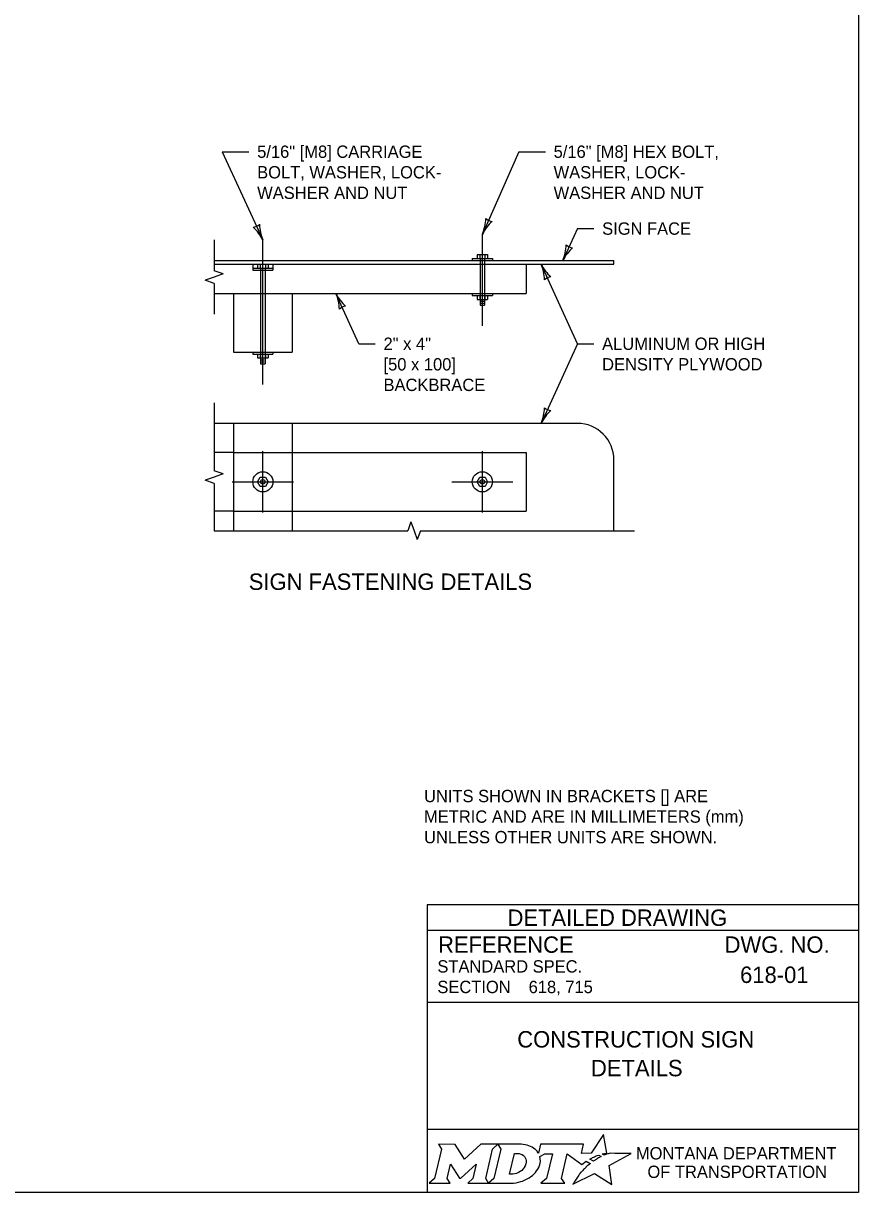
# Model space of a CAD drawing. Extents: x 49991.4 to 50021, y 49987.6 to 50011.4.
# Drawn here: x 50012.69 to 50016.75, y 49987.8 to 49993.49 of the extents above; entities that cross this region are included whole.
import ezdxf

# ---------------------------------------------------------------- set-up
doc = ezdxf.new("R2010")
doc.units = 0
for name, color, linetype in [('Default', 7, 'Continuous'), ('Level 1', 7, 'Continuous'), ('Level 2', 7, 'Continuous'), ('Level 3', 7, 'Continuous'), ('Level 4', 7, 'Continuous'), ('Level 5', 7, 'Continuous'), ('Level 6', 7, 'Continuous')]:
    doc.layers.add(name, color=color, linetype=linetype)

msp = doc.modelspace()

# ---------------------------------------------------------------- linework, layer by layer
at = {"layer": 'Default'}
for points in [[(50015.5126, 49987.9811), (50015.5023, 49987.9867), (50015.5139, 49987.9895), (50015.5255, 49987.9915), (50015.5081, 49988.0816), (50015.4486, 49987.9903), (50015.4013, 49987.9896), (50015.4116, 49988.0337), (50015.2024, 49988.0338), (50015.1923, 49987.9913), (50015.1865, 49987.9996)], [(50014.7056, 49988.0338), (50014.7197, 49988.0104), (50014.6862, 49987.8671), (50014.6605, 49987.8446), (50014.7621, 49987.8446), (50014.7486, 49987.8674), (50014.7648, 49987.9375), (50014.8085, 49987.8685), (50014.8138, 49987.8685), (50014.8889, 49987.938), (50014.8725, 49987.8669), (50014.8478, 49987.8449), (50014.9494, 49987.8449), (50014.9356, 49987.8682), (50014.9688, 49988.0106)], [(50014.9688, 49988.0106), (50014.9941, 49988.0338), (50014.9117, 49988.0338), (50014.8321, 49987.9608), (50014.7876, 49988.0335), (50014.7056, 49988.0338)], [(50015.1077, 49988.0338), (50014.9941, 49988.0338), (50015.0088, 49988.0109), (50014.9749, 49987.8671), (50014.9494, 49987.8449), (50015.06, 49987.8449)], [(50015.1317, 49987.9471), (50015.1305, 49987.939), (50015.1273, 49987.9297), (50015.1231, 49987.9215), (50015.1175, 49987.914), (50015.111, 49987.9071), (50015.1031, 49987.9008), (50015.0948, 49987.8961), (50015.0857, 49987.8922), (50015.0766, 49987.8899), (50015.0674, 49987.889), (50015.0515, 49987.889), (50015.0751, 49987.989), (50015.0911, 49987.989), (50015.0987, 49987.9884), (50015.1063, 49987.9865), (50015.1129, 49987.9835), (50015.119, 49987.9793), (50015.1238, 49987.9743), (50015.1275, 49987.9683), (50015.1302, 49987.9621), (50015.1318, 49987.9547), (50015.1318, 49987.9517), (50015.1317, 49987.9471)], [(50015.1991, 49987.9747), (50015.2237, 49987.9878), (50015.2606, 49987.9878), (50015.232, 49987.8673), (50015.2045, 49987.8446), (50015.3207, 49987.8446), (50015.3037, 49987.8675), (50015.3319, 49987.9877), (50015.4032, 49987.936), (50015.4243, 49987.9511), (50015.444, 49987.9402)], [(50015.3882, 49987.8843), (50015.3729, 49987.8599), (50015.3682, 49987.8524), (50015.3624, 49987.8438), (50015.3601, 49987.8395), (50015.4654, 49987.8926), (50015.5493, 49987.8375), (50015.5362, 49987.9302), (50015.6431, 49987.9886), (50015.5938, 49987.9894), (50015.5637, 49987.9898), (50015.5429, 49987.9901), (50015.5361, 49987.9886), (50015.5312, 49987.9874), (50015.5228, 49987.9851), (50015.5126, 49987.9811)], [(50015.4622, 49987.9535), (50015.4598, 49987.9518), (50015.4415, 49987.9614), (50015.4518, 49987.9671), (50015.4559, 49987.9693), (50015.4645, 49987.9733), (50015.4702, 49987.9759), (50015.4781, 49987.9789), (50015.4854, 49987.9816), (50015.4972, 49987.9742), (50015.4932, 49987.9721), (50015.4886, 49987.9696), (50015.4844, 49987.9674), (50015.4794, 49987.9645), (50015.4775, 49987.9634), (50015.4748, 49987.9618), (50015.4723, 49987.9604), (50015.47, 49987.9588), (50015.4674, 49987.957), (50015.4647, 49987.9552), (50015.4622, 49987.9535)], [(50015.1057, 49987.8522), (50015.1141, 49987.8548), (50015.1271, 49987.8602), (50015.1475, 49987.8712)], [(50015.4021, 49987.9004), (50015.4021, 49987.9004)]]:
    msp.add_lwpolyline(points, dxfattribs=at)
for centre, radius, start, end in [((50015.0868, 49987.9727), 0.1183, 300.9103, 339.1383), ((50015.1308, 49987.9554), 0.0709, 339.5329, 15.8582)]:
    msp.add_arc(centre, radius, start, end, dxfattribs=at)
for centre, major_axis, ratio, start_param, end_param in [((50015.1056, 49987.9864), (0.0834, -0.0037), 0.568097, 0.61298, 1.570796), ((50015.1612, 49987.9937), (0.0361, -0.0295), 0.469099, 1.225588, 1.570796), ((50015.4329, 49987.9305), (-0.0112, -0.0097), 0.021651, 3.157348, 6.283185), ((50015.3952, 49987.8923), (-0.00694, -0.00806), 0.008222, 0, 3.137361), ((50015.4119, 49987.9106), (-0.0098, -0.0102), 0.016458, 3.141593, 6.279097), ((50015.0603, 49987.9932), (0, 0.1484), 0.987302, 3.139398, 3.456847)]:
    msp.add_ellipse(centre, major_axis=major_axis, ratio=ratio, start_param=start_param, end_param=end_param, dxfattribs=at)
at = {"layer": 'Level 1'}
for p, q in [((50013.614, 49992.3335), (50015.5597, 49992.3335)), ((50013.614, 49992.3156), (50015.1326, 49992.3156)), ((50013.8258, 49992.3156), (50013.8771, 49992.3156)), ((50014.8703, 49992.343), (50014.9683, 49992.343)), ((50014.8703, 49992.343), (50014.8703, 49992.3335)), ((50014.8938, 49992.362), (50014.8938, 49992.343)), ((50014.8938, 49992.362), (50014.9451, 49992.362)), ((50014.9068, 49992.362), (50014.9068, 49992.343)), ((50014.9321, 49992.362), (50014.9321, 49992.343)), ((50014.9451, 49992.362), (50014.9451, 49992.343)), ((50014.9683, 49992.343), (50014.9683, 49992.3335)), ((50015.1326, 49992.3156), (50015.1326, 49992.1731)), ((50015.1326, 49992.3156), (50015.5597, 49992.3156)), ((50015.5597, 49992.3156), (50015.5597, 49992.3335)), ((50013.614, 49992.1731), (50015.1326, 49992.1731)), ((50013.709, 49992.1731), (50013.709, 49991.8881)), ((50013.994, 49992.1731), (50013.994, 49991.8881)), ((50014.8703, 49992.1731), (50014.8703, 49992.1636)), ((50014.8703, 49992.1636), (50014.9683, 49992.1636)), ((50014.8938, 49992.1636), (50014.8938, 49992.1446)), ((50014.8938, 49992.1446), (50014.9451, 49992.1446)), ((50014.9068, 49992.1636), (50014.9068, 49992.1446)), ((50014.9082, 49992.1446), (50014.9082, 49992.1161)), ((50014.913, 49992.1351), (50014.9257, 49992.1351)), ((50014.9305, 49992.1446), (50014.9305, 49992.1161)), ((50014.9321, 49992.1636), (50014.9321, 49992.1446)), ((50014.9451, 49992.1636), (50014.9451, 49992.1446)), ((50014.9683, 49992.1731), (50014.9683, 49992.1636)), ((50014.9082, 49992.1161), (50014.9305, 49992.1161)), ((50014.913, 49992.1256), (50014.9257, 49992.1256)), ((50013.709, 49991.8881), (50013.994, 49991.8881)), ((50013.8023, 49991.8881), (50013.8023, 49991.8786)), ((50013.8023, 49991.8786), (50013.9004, 49991.8786)), ((50013.8258, 49991.8786), (50013.8258, 49991.8596)), ((50013.8258, 49991.8596), (50013.8771, 49991.8596)), ((50013.8388, 49991.8786), (50013.8388, 49991.8596)), ((50013.8402, 49991.8596), (50013.8402, 49991.8311)), ((50013.8625, 49991.8596), (50013.8625, 49991.8311)), ((50013.8641, 49991.8786), (50013.8641, 49991.8596)), ((50013.8771, 49991.8786), (50013.8771, 49991.8596)), ((50013.9004, 49991.8881), (50013.9004, 49991.8786)), ((50013.8402, 49991.8311), (50013.8625, 49991.8311)), ((50013.845, 49991.8501), (50013.8577, 49991.8501)), ((50013.845, 49991.8406), (50013.8577, 49991.8406)), ((50015.382, 49991.5414), (50013.614, 49991.5414)), ((50013.709, 49991.5414), (50013.709, 49991.0192)), ((50013.994, 49991.5414), (50013.994, 49991.0192)), ((50013.709, 49991.3992), (50013.614, 49991.3992)), ((50013.994, 49991.3992), (50015.1326, 49991.3992)), ((50015.1326, 49991.3992), (50015.1326, 49991.1142)), ((50015.5597, 49991.0192), (50015.5597, 49991.3634)), ((50013.709, 49991.1142), (50013.614, 49991.1142)), ((50013.994, 49991.1142), (50015.1326, 49991.1142)), ((50016.3862, 49988.8587), (50016.3862, 49988.8587)), ((50015.1444, 49988.7993), (50015.1444, 49988.7993)), ((50015.7001, 49988.4747), (50015.7001, 49988.4747))]:
    msp.add_line(p, q, dxfattribs=at)
for points in [[(49999.3835, 49998.9992), (50016.7501, 49998.9992), (50016.7501, 49987.7988), (49999.3835, 49987.7988)], [(50013.8388, 49991.279), (50013.8641, 49991.279), (50013.8771, 49991.2571), (50013.8641, 49991.2345), (50013.8388, 49991.2345), (50013.8258, 49991.2571)], [(50014.9063, 49991.279), (50014.9324, 49991.279), (50014.9446, 49991.2571), (50014.9324, 49991.2345), (50014.9063, 49991.2345), (50014.8934, 49991.2571)]]:
    msp.add_lwpolyline(points, close=True, dxfattribs=at)
for centre, radius in [((50013.8513, 49991.2567), 0.049), ((50014.9192, 49991.2567), 0.049), ((50013.8513, 49991.2567), 0.0111), ((50014.9192, 49991.2567), 0.0111)]:
    msp.add_circle(centre, radius, dxfattribs=at)
msp.add_ellipse((50015.3817, 49991.3634), major_axis=(0.178, 0), ratio=0.999996, start_param=0, end_param=1.570796, dxfattribs=at)
at = {"layer": 'Level 3'}
for p, q in [((50013.6535, 49992.863), (50013.8514, 49992.4335)), ((50013.6535, 49992.863), (50013.7835, 49992.863)), ((50015.0961, 49992.863), (50014.9194, 49992.462)), ((50015.0961, 49992.863), (50015.2261, 49992.863)), ((50015.3821, 49992.4889), (50015.3111, 49992.3335)), ((50015.3821, 49992.4889), (50015.4621, 49992.4889)), ((50015.3821, 49991.9286), (50015.2054, 49992.3156)), ((50014.3184, 49991.9286), (50014.2068, 49992.1731)), ((50014.3184, 49991.9286), (50014.3984, 49991.9286)), ((50015.3821, 49991.9286), (50015.2054, 49991.5414)), ((50015.3821, 49991.9286), (50015.4621, 49991.9286))]:
    msp.add_line(p, q, dxfattribs=at)
for centre, radius, start, end in [((50014.7035, 49992.5495), 0.233, 337.9464, 357.1963), ((50014.9734, 49992.5783), 0.0548, 227.2579, 262.9803), ((50013.7976, 49992.5498), 0.0548, 276.9845, 312.7068), ((50013.6451, 49992.3253), 0.233, 27.673, 46.9228), ((50014.0568, 49992.5185), 0.2223, 182.3017, 202.4852), ((50015.1171, 49992.3602), 0.2223, 132.5751, 152.7586), ((50015.0947, 49992.4198), 0.233, 338.2723, 357.5222), ((50015.5094, 49992.2329), 0.2223, 132.901, 153.0845), ((50015.3644, 49992.4501), 0.0548, 227.5838, 263.3062), ((50014.9996, 49992.2317), 0.2223, 1.9969, 22.1804), ((50015.4123, 49992.4227), 0.233, 207.3682, 226.6181), ((50015.2587, 49992.199), 0.0548, 96.6797, 132.4021), ((50014.0012, 49992.0891), 0.2223, 1.9899, 22.1735), ((50014.414, 49992.28), 0.233, 207.3612, 226.6111), ((50014.2603, 49992.0563), 0.0548, 96.6728, 132.3951), ((50014.9889, 49991.6276), 0.233, 338.292, 357.5418), ((50015.4037, 49991.4408), 0.2223, 132.9207, 153.1042), ((50015.2586, 49991.658), 0.0548, 227.6035, 263.3258)]:
    msp.add_arc(centre, radius, start, end, dxfattribs=at)
at = {"layer": 'Level 4'}
for p, q in [((50013.8023, 49992.3156), (50013.8023, 49992.2871)), ((50013.8258, 49992.3156), (50013.8258, 49992.2966)), ((50013.8388, 49992.3156), (50013.8388, 49992.2966)), ((50013.8641, 49992.3156), (50013.8641, 49992.2966)), ((50013.8771, 49992.3156), (50013.8771, 49992.2966)), ((50013.9004, 49992.3156), (50013.9004, 49992.2871)), ((50014.9082, 49992.343), (50014.9082, 49992.1446)), ((50014.9305, 49992.343), (50014.9305, 49992.1446)), ((50013.8023, 49992.2966), (50013.9004, 49992.2966)), ((50013.8023, 49992.2871), (50013.9004, 49992.2871)), ((50013.8402, 49992.2966), (50013.8402, 49991.8596)), ((50013.8625, 49992.2966), (50013.8625, 49991.8596)), ((50013.709, 49991.3992), (50013.994, 49991.3992)), ((50013.709, 49991.1142), (50013.994, 49991.1142))]:
    msp.add_line(p, q, dxfattribs=at)
at = {"layer": 'Level 5'}
for p, q in [((50013.8514, 49992.0781), (50013.8514, 49992.4335)), ((50014.9194, 49992.2467), (50014.9194, 49992.462)), ((50014.9194, 49992.0161), (50014.9194, 49992.2467)), ((50013.8514, 49991.7311), (50013.8514, 49992.0781)), ((50013.8514, 49991.2567), (50013.8514, 49991.4057)), ((50014.9193, 49991.2567), (50014.9193, 49991.4057)), ((50013.7023, 49991.2567), (50013.8513, 49991.2567)), ((50013.8514, 49991.1077), (50013.8514, 49991.2567)), ((50013.8514, 49991.2567), (50014.0003, 49991.2567)), ((50014.7703, 49991.2567), (50014.9192, 49991.2567)), ((50014.9192, 49991.2567), (50015.0682, 49991.2567)), ((50014.9193, 49991.1077), (50014.9193, 49991.2567)), ((50016.7501, 49989.1988), (50014.6501, 49989.1988)), ((50014.6501, 49989.1988), (50014.6501, 49987.7988)), ((50016.7501, 49989.0738), (50014.6501, 49989.0738)), ((50016.3862, 49988.8587), (50016.3862, 49988.8587)), ((50015.1444, 49988.7993), (50015.1444, 49988.7993)), ((50016.7501, 49988.7238), (50014.6501, 49988.7238)), ((50015.7001, 49988.4747), (50015.7001, 49988.4747)), ((50016.7501, 49988.1057), (50014.6501, 49988.1057))]:
    msp.add_line(p, q, dxfattribs=at)
at = {"layer": 'Level 6'}
for p, q in [((50013.614, 49992.4335), (50013.614, 49992.2841)), ((50013.614, 49992.2533), (50013.5705, 49992.2379)), ((50013.6574, 49992.2687), (50013.614, 49992.2841)), ((50013.6574, 49992.2687), (50013.614, 49992.2533)), ((50013.614, 49992.2225), (50013.5705, 49992.2379)), ((50013.614, 49992.2225), (50013.614, 49992.0731)), ((50013.614, 49991.6414), (50013.614, 49991.3111)), ((50013.6574, 49991.2957), (50013.614, 49991.3111)), ((50013.6574, 49991.2957), (50013.614, 49991.2803)), ((50013.614, 49991.2803), (50013.5705, 49991.2649)), ((50013.614, 49991.2495), (50013.5705, 49991.2649)), ((50013.614, 49991.2495), (50013.614, 49991.0192)), ((50014.5715, 49991.0626), (50014.5561, 49991.0192)), ((50014.5715, 49991.0626), (50014.5868, 49991.0192)), ((50013.614, 49991.0192), (50014.5561, 49991.0192)), ((50014.5868, 49991.0192), (50014.6022, 49990.9758)), ((50014.6176, 49991.0192), (50014.6022, 49990.9758)), ((50014.6176, 49991.0192), (50015.6597, 49991.0192))]:
    msp.add_line(p, q, dxfattribs=at)

# ---------------------------------------------------------------- texts
at = {"layer": 'Default'}
for s, p in [('MONTANA DEPARTMENT', (50015.6663, 49987.96)), ('OF TRANSPORTATION', (50015.7225, 49987.87))]:
    msp.add_text(s, height=0.06, dxfattribs=at).set_placement(p)
at = {"layer": 'Level 2'}
for s, height, p in [('5/16" [M8] CARRIAGE', 0.06, (50013.8235, 49992.833)), ('5/16" [M8] HEX BOLT,', 0.06, (50015.2661, 49992.833)), ('BOLT, WASHER, LOCK-', 0.06, (50013.8235, 49992.733)), ('WASHER, LOCK-', 0.06, (50015.2661, 49992.733)), ('WASHER AND NUT', 0.06, (50013.8235, 49992.633)), ('WASHER AND NUT', 0.06, (50015.2661, 49992.633)), ('SIGN FACE', 0.06, (50015.5021, 49992.4589)), ('2" x 4"', 0.06, (50014.4384, 49991.8986)), ('ALUMINUM OR HIGH', 0.06, (50015.5021, 49991.8986)), ('[50 x 100]', 0.06, (50014.4384, 49991.7986)), ('DENSITY PLYWOOD', 0.06, (50015.5021, 49991.7986)), ('BACKBRACE', 0.06, (50014.4384, 49991.6986)), ('SIGN FASTENING DETAILS', 0.08, (50013.7826, 49990.7309)), ('UNITS SHOWN IN BRACKETS [] ARE ', 0.06, (50014.6356, 49989.6983)), ('METRIC AND ARE IN MILLIMETERS (mm) ', 0.06, (50014.6356, 49989.5983)), ('UNLESS OTHER UNITS ARE SHOWN.', 0.06, (50014.6356, 49989.4983)), ('618-01', 0.08, (50016.1734, 49988.8187)), ('618, 715', 0.06, (50015.1445, 49988.7693)), ('CONSTRUCTION SIGN', 0.08, (50015.0891, 49988.5047)), ('DETAILS', 0.08, (50015.4478, 49988.3647))]:
    msp.add_text(s, height=height, dxfattribs=at).set_placement(p)
at = {"layer": 'Level 5'}
for s, height, p in [('DETAILED DRAWING', 0.0799, (50015.0418, 49989.0963)), ('REFERENCE', 0.08, (50014.7037, 49988.9654)), ('DWG. NO.', 0.08, (50016.0979, 49988.9654)), ('STANDARD SPEC.', 0.06, (50014.7004, 49988.8694)), ('SECTION', 0.06, (50014.7004, 49988.7694))]:
    msp.add_text(s, height=height, dxfattribs=at).set_placement(p)

doc.saveas('drawing.dxf')
